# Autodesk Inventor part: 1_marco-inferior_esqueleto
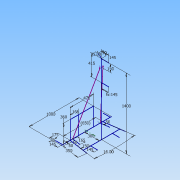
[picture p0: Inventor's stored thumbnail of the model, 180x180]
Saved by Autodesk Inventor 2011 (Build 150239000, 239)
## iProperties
Created: 2020-11
Part Number: 1_marco-inferior_esqueleto
Document SubType Name: Modeling
Designer: PC
Density: 1 g/cm^3
Author: PC
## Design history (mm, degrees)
sketch "Sketch1"
  geometry: L1 (-500, 0)-(500, 0); L2 (-325, 0)-(-347.964, -163.394); L3 (0, -182.193)-(0, 30.366) reference; L4 (325, 0)-(347.964, -163.394); L5 (-380.669, -396.107)-(-331.959, -49.513); L6 (380.669, -396.107)-(331.959, -49.513); L7 (-367.162, -300)-(367.162, -300); L8 (-217.162, -300)-(-217.162, -445); L9 (217.162, -300)-(217.162, -445); L10 (-475, 0)-(-475, 145); L11 (475, 0)-(475, 145); L12 (-274.509, 0)-(-298.45, -170.353); L13 (274.509, 0)-(298.45, -170.353); 4 further points
  constraints: 24 end point, 8 symmetric about line, 7 point on line, 3 coincident, 3 parallel, 2 perpendicular, 1 collinear, 1 horizontal, 1 midpoint
  dimensions: "d0" = 1000 distance of L1.start L1.end; "d1" = 165 distance of L2.start L2.end; "d2" = 16 deg angle of L4 L2; "d4" = 175 distance of L1.start L2.start; "d5" = 650 distance of L4.start L2.start (derived); "d6" = 50 distance of L2.start L5.end; "d7" = 350 distance of L5.start L5.end; "d11" = 300 distance between parallel lines of L7 L1; "d29" = 145 distance of L8.start L8.end; "d30" = 150 distance from line of L7.start L8; "d31" = 145 distance of L10.start L10.end; "d32" = 25 distance from line of L1.start L10; "d35" = 50 distance between parallel lines of L12 L2; "d36" = 50 distance between parallel lines of L4 L13
sketch "Sketch2"
  geometry: L1 (325, 0)-(-145, 0); L2 (-145, 0)-(-145, 360); L3 (-145, 360)-(325, 360); L4 (325, 360)-(325, 0); L5 (157, 0)-(157, 360); 1 further point
  constraints: 10 end point, 2 parallel, 2 perpendicular, 2 point on line, 1 horizontal
  dimensions: "d8" = 360 distance of L3.end L1.start; "d9" = 470 distance of L2.end L3.end; "d10" = 168 distance between parallel lines of L4 L5
sketch "Sketch3"
  geometry: L1 (-300, 0)-(-300, 1400); L2 (-300, 1400)-(-445, 1400); L3 (-300, 985)-(-445, 985); L4 (-300, 1400)-(-236.36, 1463.64); 2 further points
  constraints: 8 end point, 2 point on line, 1 parallel, 1 perpendicular, 1 vertical
  dimensions: "d12" = 1400 distance of L1.start L1.end; "d26" = 145 distance of L1.end L2.end; "d27" = 145 distance of L3.start L3.end (= d26); "d28" = 415 distance between parallel lines of L2 L3; "d33" = 150 distance of point (-300, 1250) L1.end; "d37" = 45 deg angle of L2 L4; "d38" = 90 distance of L1.end L4.end
sketch "3D Sketch1"
